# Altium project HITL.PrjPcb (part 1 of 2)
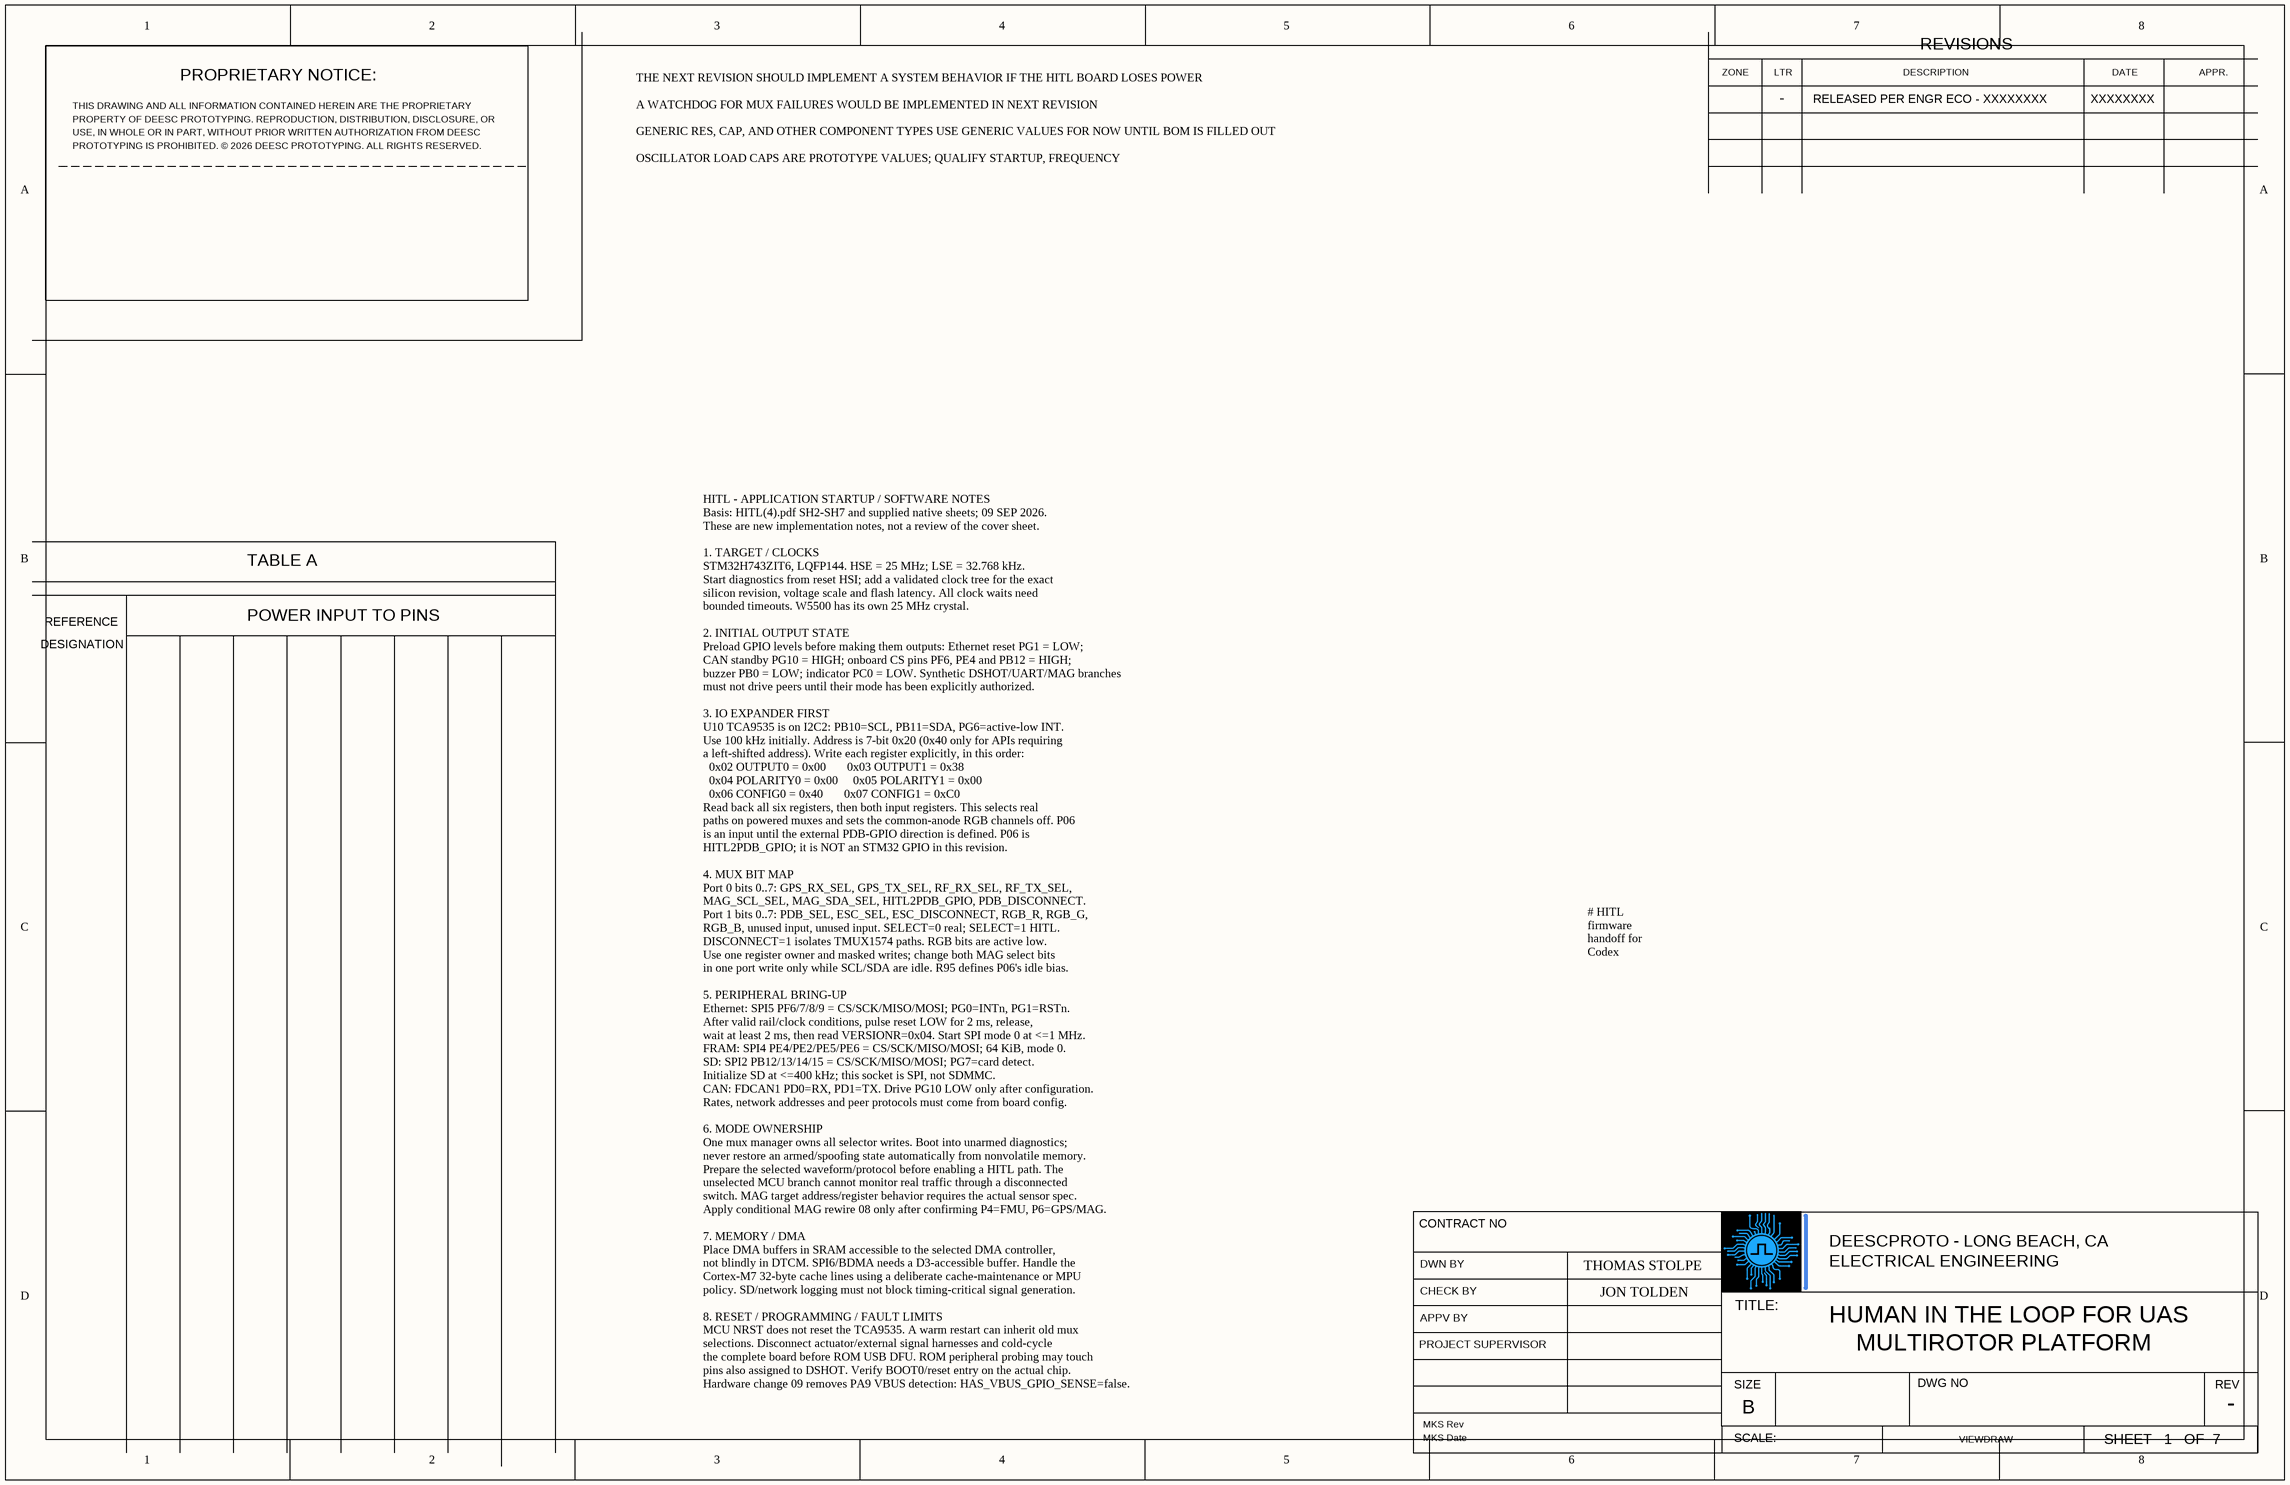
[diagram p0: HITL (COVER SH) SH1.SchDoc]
7 sheets, 198 parts. Net scope: global (net labels, ports and power ports of the same name join across sheets).
Board file: HITL R DRAFT 3 PCB.PcbDoc
Sheets:
  HITL (COVER SH) SH1.SchDoc
  HITL (PWR) SH2.SchDoc
  HITL (MCU) SH3.SchDoc
  HITL (MUX) SH4.SchDoc
  HITL (MEMORY) SH5.SchDoc
  HITL (INTRFACE 1) SH6.SchDoc
  HITL (INTRFACE 2) SH7.SchDoc

## Sheet HITL (COVER SH) SH1.SchDoc
size Tabloid; SheetNumber: 1; SheetTotal: 7

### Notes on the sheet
- THE NEXT REVISION SHOULD IMPLEMENT A SYSTEM BEHAVIOR IF THE HITL BOARD LOSES POWER
- A WATCHDOG FOR MUX FAILURES WOULD BE IMPLEMENTED IN NEXT REVISION
- GENERIC RES, CAP, AND OTHER COMPONENT TYPES USE GENERIC VALUES FOR NOW UNTIL BOM IS FILLED OUT
- OSCILLATOR LOAD CAPS ARE PROTOTYPE VALUES; QUALIFY STARTUP, FREQUENCY
- RELEASED PER ENGR ECO - XXXXXXXX
- XXXXXXXX
- # HITL firmware handoff for Codex
  **Board baseline:** `HITL(4).pdf`, SH2-SH7; native source cross-check dated 09 September 2026. This is a hardware contract and implementation plan, not completed or tested firmware. The separate hardware report contains only edit items 01-10. No cover-sheet review is included.
  ## 1. Source boundary and build profile
  Five circuit sources are the `(4).SchDoc` versions: power SH2, MCU SH3, mux SH4, memory SH5, connectors SH7. The latest supplied SH6 native is `(3).SchDoc`. Its R29 is DNI while the current PDF shows 10 kOhm; hardware change 10 proposes a fitted 0-ohm ground strap and requires synchronized source/BOM/PDF. Do not merge the unrelated PODIUM PDB into this board definition. [S01, N2-N7]
  Create an explicit board revision/profile in the project. The post-edit profile must record these dependencies:
  | Capability / hardware option | Required software meaning |
  | --- | --- |
  | Change 06, new R95 fitted | P06's isolated branch has a 10 kOhm pull-down; P06 direction is still not automatically an output. |
  | Change 08, conditional MAG rewire | Set `MAG_COMMON_SIDE=FMU_IN` only after P4=FMU and P6=real GPS/MAG are physically confirmed and the rewire is applied. Otherwise disable MAG emulation pending an approved alternative harness contract. |
  | Change 09, R1 and D1 not fitted | Set `HAS_VBUS_GPIO_SENSE=false`. PA9 cannot report USB attachment in this population. |
  | No external hardware watchdog / bypass | Software must not advertise guaranteed real-path control after HITL power loss or an unresponsive expander. |
  | USB programming use | ROM DFU is the programming path; no application USB data class is requested by this handoff. |
  The MCU is **STM32H743ZIT6, LQFP144**. The Ethernet controller is an external **W5500 on SPI5**, not an RMII PHY attached to the STM32 Ethernet MAC. SD is **SPI2**, not SDMMC. FRAM is **SPI4**. An I2C2 TCA9535 controls switch selection and RGB. These are actual schematic assignments; firmware policy below is a proposed implementation baseline. [N3-N6]
  The eFuses select USB/PDB power autonomously. Their fault/current/enable nodes are not routed to MCU measurement/control pins in this drawing. Do not fabricate software rail-current telemetry, programmable eFuse thresholds, or accessory power switches. External +5 V/+3.3 V connector pins are powered directly from those rails. [N2, N7]
  ## 2. Project setup and startup sequence
  Generate a clean STM32H743ZIT6 project and check in the `.ioc`, toolchain/package versions, linker script, board pin definitions and populated-hardware profile. Use CMSIS/HAL deliberately; RTOS use is optional. Peripheral ownership, timeout handling and deterministic output behavior matter more than the choice of scheduler.
  ### Stage A - establish a diagnostic state
  At reset, use the internal HSI clock to begin diagnostics. The populated HSE is **25 MHz** and LSE is **32.768 kHz**. Set `HSE_VALUE`/`LSE_VALUE` accordingly and configure the HSE as a crystal, not an external bypass clock. Oscillator waits must time out; an unavailable LSE must not hang programming or basic diagnostics. Log the chip revision and clock failure state. [N3; D15]
  Do not select 480 MHz merely because the library description says 480 MHz. Confirm the exact silicon revision, applicable errata, supply mode, voltage scale, flash latency, PLL limits and bus/kernel prescalers. Choose the validated operating point needed by measured workload. Derive each timer/SPI/I2C/UART kernel frequency from the actual clock tree; an APB peripheral clock is not always its timer clock. [D15, D16]
  Preload output latches before changing GPIO modes: PF6/PE4/PB12 CS high; PG1 Ethernet reset low; PG10 CAN standby high; PC0 indicator low; PB0 buzzer low. Other external chip selects become high before their SPI peripheral is enabled, once peer voltage/power is known. Initially disable timer output enables and UART transmitters on synthetic branches; use high-impedance GPIO states rather than transmitting a guessed neutral value. Maintain SWD access.
  ### Stage B - establish switch ownership before external traffic
  Initialize I2C2 at a conservative **100 kHz** and address U10 at **7-bit 0x20**. Some STM32 HAL calls expect `0x20 << 1`; use the address form expected by the actual API, not a mixture. Apply the explicit register sequence in Section 4 and compare readback. An I2C ACK alone does not prove correct pin state. [N4; D06]
  The application should start **unarmed**. Real-path selection is not an instruction to generate actuator commands. Do not initialize synthetic UART/timer outputs and assume all switches have just reset; a warm MCU reset may leave the expander latched in a previous mode. Testing initially requires external actuator harnesses disconnected.
  ### Stage C - independent peripheral diagnostics
  Bring up Ethernet, FRAM, SD and CAN separately with bounded transactions. Report each failure independently. SD absence or an unplugged Ethernet cable must not stop the scheduler or mutate mux selection. No startup error should cause an automatic transition into a synthetic-output mode.
  ### Stage D - explicit operating authorization
  Enable an emulation channel only after its peer pin directions, supply level, timing, protocol configuration and hardware profile are known. The host command must identify the intended test mode. Persist configuration with a version and CRC, but do not restore the last armed state automatically. Settings that are absent or incompatible should prevent that mode from arming.
  ## 3. MCU pin contract
  Physical pin numbers below are for the **144-pin** package, not connector numbers. Named nets are extracted from N3. AF selections were checked against the STM32 alternate-function tables, but a complete CubeMX/clock/DMA build is still required. Software-controlled CS rows deliberately use GPIO rather than hardware NSS. [N3; D15]
  | MCU port | Pin | Net | Function | AF | Use |
  | --- | --- | --- | --- | --- | --- |
  | PF6 | 18 | ETH_SCSN | SPI5 CS | GPIO | W5500 CS, active low |
  | PF7 | 19 | ETH_SCLK | SPI5 SCK | 5 | W5500 clock |
  | PF8 | 20 | ETH_MISO | SPI5 MISO | 5 | W5500 -> MCU |
  | PF9 | 21 | ETH_MOSI | SPI5 MOSI | 5 | MCU -> W5500 |
  | PG0 | 56 | ETH_INTn | EXTI / input | GPIO | W5500 INTn, active low |
  | PG1 | 57 | ETH_RSTn | Reset output | GPIO | W5500 RSTn, active low |
  | PE2 | 1 | SPI4_SCK | SPI4 SCK | 5 | FRAM clock |
  | PE5 | 4 | SPI4_MISO | SPI4 MISO | 5 | FRAM -> MCU |
  | PE6 | 5 | SPI4_MOSI | SPI4 MOSI | 5 | MCU -> FRAM |
  | PE4 | 3 | FRAM_CS | SPI4 CS | GPIO | FRAM CS, active low |
  | PB12 | 73 | SD_DATA3 | SPI2 CS | GPIO | SD DAT3/CS, active low |
  | PB13 | 74 | SD_CLK | SPI2 SCK | 5 | SD clock |
  | PB14 | 75 | SD_DATA0 | SPI2 MISO | 5 | SD DAT0 -> MCU |
  | PB15 | 76 | SD_CMD | SPI2 MOSI | 5 | MCU -> SD CMD |
  | PG7 | 92 | SD_DET | Card-detect input | GPIO | External pull-up; verify insertion polarity |
  | PB10 | 69 | IO_EXP_SCL | I2C2 SCL | 4 | Expander bus, MCU controller |
  | PB11 | 70 | IO_EXP_SDA | I2C2 SDA | 4 | Expander bus, open drain |
  | PG6 | 91 | IO_EXP_INT | EXTI / input | GPIO | Expander INT, active low |
  | PA8 | 100 | HITL_MAG_SCL | I2C3 SCL | 4 | MAG emulation bus; target role |
  | PC9 | 99 | HITL_MAG_SDA | I2C3 SDA | 4 | MAG emulation bus; open drain |
  | PE9 | 60 | HITL_DSHOT1 | TIM1 CH1 | 1 | HITL DSHOT1 branch |
  | PE11 | 64 | HITL_DSHOT2 | TIM1 CH2 | 1 | HITL DSHOT2 branch |
  | PE13 | 66 | HITL_DSHOT3 | TIM1 CH3 | 1 | HITL DSHOT3 branch |
  | PE14 | 67 | HITL_DSHOT4 | TIM1 CH4 | 1 | HITL DSHOT4 branch |
  | PB6 | 136 | FMU_UART1_TX | USART1 TX | 7 | Direct FMU telemetry |
  | PB7 | 137 | FMU_UART1_RX | USART1 RX | 7 | Direct FMU telemetry |
  | PE8 | 59 | HITL_PDB_UART_TX | UART7 TX | 7 | PDB synthetic UART branch |
  | PE7 | 58 | HITL_PDB_UART_RX | UART7 RX | 7 | PDB synthetic UART branch |
  | PE1 | 142 | HITL_RF_UART_TX | UART8 TX | 8 | RF synthetic UART branch |
  | PE0 | 141 | HITL_RF_UART_RX | UART8 RX | 8 | RF synthetic UART branch |
  | PD14 | 85 | UART8_CTS | UART8 CTS | 8 | Test point only; flow control disabled initially |
  | PD15 | 86 | UART8_RTS | UART8 RTS | 8 | Test point only; flow control disabled initially |
  | PC6 | 96 | HITL_GPS_TX | USART6 TX | 7 | GPS synthetic UART branch |
  | PC7 | 97 | HITL_GPS_RX | USART6 RX | 7 | GPS synthetic UART branch |
  | PD0 | 114 | CAN_RX | FDCAN1 RX | 9 | TCAN1042 RXD |
  | PD1 | 115 | CAN_TX | FDCAN1 TX | 9 | TCAN1042 TXD |
  | PG10 | 125 | CAN_STB | Standby output | GPIO | CAN_STB: high = standby |
  | PB0 | 46 | BUZZER | TIM3 CH3 | 2 | Q1 buzzer drive, active high |
  | PC0 | 26 | LED | LED output | GPIO | D6 blue LED, active high |
  | PA11 | 103 | DOUT_N | USB OTG FS DM | 10 | USB programming data |
  | PA12 | 104 | DOUT_P | USB OTG FS DP | 10 | USB programming data |
  | PA9 | 101 | USB_VBUS_SNS | VBUS input option | GPIO | No USB presence sensing after hardware change 09 |
  | PA4 | 40 | SPI1_CS | SPI1 CS | GPIO | External connector P5 |
  | PA5 | 41 | SPI1_SCK | SPI1 SCK | 5 | External connector P5 |
  | PA6 | 42 | SPI1_MISO | SPI1 MISO | 5 | External connector P5 |
  | PA7 | 43 | SPI1_MOSI | SPI1 MOSI | 5 | External connector P5 |
  | PA15 | 110 | SPI3_CS | SPI3 CS | GPIO | External connector P7 |
  | PC10 | 111 | SPI3_SCK | SPI3 SCK | 6 | External connector P7 |
  | PC11 | 112 | SPI3_MISO | SPI3 MISO | 6 | External connector P7 |
  | PC12 | 113 | SPI3_MOSI | SPI3 MOSI | 6 | External connector P7 |
  | PG8 | 93 | SPI6_CS | SPI6 CS | GPIO | PG8 is software CS, NOT SPI6 hardware NSS |
  | PG13 | 128 | SPI6_SCK | SPI6 SCK | 5 | External connector P10 |
  | PG12 | 127 | SPI6_MISO | SPI6 MISO | 5 | External connector P10 |
  | PG14 | 129 | SPI6_MOSI | SPI6 MOSI | 5 | External connector P10 |
  | PB8 | 139 | I2C1_SCL | I2C1 SCL | 4 | External connector J7 |
  | PB9 | 140 | I2C1_SDA | I2C1 SDA | 4 | External connector J7 |
  | PB5 | 135 | I2C1_GPIO | Auxiliary GPIO | GPIO | I2C1_GPIO test point; not serial data |
  | PD12 | 81 | I2C4_SCL | I2C4 SCL | 4 | External connector J8 |
  | PD13 | 82 | I2C4_SDA | I2C4 SDA | 4 | External connector J8 |
  | PA0 | 34 | UART4_TX | UART4 TX | 8 | External connector P12 |
  | PA1 | 35 | UART4_RX | UART4 RX | 8 | External connector P12 |
  | PD8 | 77 | USART3_TX | USART3 TX | 7 | External connector P13 |
  | PD9 | 78 | USART3_RX | USART3 RX | 7 | External connector P13 |
  | PA2 | 36 | USART2_TX | USART2 TX | 7 | External connector P14 |
  | PA3 | 37 | USART2_RX | USART2 RX | 7 | External connector P14 |
  | PA13(JTMS-SWDIO) | 105 | SWDIO | SWDIO | 0 | Debugger reserved |
  | PA14(JTCK/SWCLK) | 109 | SWCLK | SWCLK | 0 | Debugger reserved |
  | PB3(JTDO/TRACESWO) | 133 | SWO | SWO | 0 | Optional debugger trace |
  The spare breakout signals are PF2/PF3/PF4/PF5/PF10, PC1, PC2_C, PC3_C, PC4/PC5, PB1, PF11/PF12, PE12, PF14/PF15. **PC2_C/PC3_C are analog-switch pads**, so a digital-use plan must explicitly handle the relevant internal analog-switch configuration and electrical/speed restrictions. Do not silently treat them as ordinary unrestricted GPIO. PF15 is a spare breakout here, not `HITL2PDB_GPIO`. [N3, N7; D15]
  ## 4. TCA9535 register and bit contract
  A0/A1/A2 are tied low. U10 has a 7-bit address of 0x20. It does not share the external I2C1/I2C4 connectors. Software must have **one owner** for its output shadow registers; LEDs and mux tasks must not overwrite one another's bits. Use locked masked updates rather than whole-port writes from unrelated drivers. [N4]
  | Register | Address | Initial value | Interpretation |
  | --- | --- | --- | --- |
  | OUTPUT0 | 0x02 | 0x00 | All real-path selects low; PDB disconnect low; P06 latch low. |
  | OUTPUT1 | 0x03 | 0x38 | PDB/ESC selects low, ESC disconnect low, R/G/B cathodes high (off). |
  | POLARITY0 | 0x04 | 0x00 | Input readings not inverted. |
  | POLARITY1 | 0x05 | 0x00 | Input readings not inverted. |
  | CONFIG0 | 0x06 | 0x40 | P06 input; other port-0 bits outputs. |
  | CONFIG1 | 0x07 | 0xC0 | P16/P17 inputs; other port-1 bits outputs. |
  Write OUTPUT0 and OUTPUT1 before CONFIG0/CONFIG1. Write the two polarity registers explicitly. Read back all six registers and then INPUT0 (0x00) and INPUT1 (0x01). Do not issue a six-byte burst assuming the address pointer walks through every register; use explicitly addressed operations appropriate to this device. The mapping and initial values are board-specific calculations from the native wiring. [N4; D06]
  | Port.bit | U10 pin | Net | Meaning |
  | --- | --- | --- | --- |
  | P0.0 | 4 | GPS_RX_SEL | 0 real / 1 HITL |
  | P0.1 | 5 | GPS_TX_SEL | 0 real / 1 HITL |
  | P0.2 | 6 | RF_RX_SEL | 0 real / 1 HITL |
  | P0.3 | 7 | RF_TX_SEL | 0 real / 1 HITL |
  | P0.4 | 8 | MAG_SCL_SEL | 0 real / 1 HITL |
  | P0.5 | 9 | MAG_SDA_SEL | 0 real / 1 HITL |
  | P0.6 | 10 | HITL2PDB_GPIO | PDB GPIO data branch; input until ownership is defined |
  | P0.7 | 11 | PDB_DISCONNECT | 1 isolates U9 |
  | P1.0 | 13 | PDB_SEL | 0 real / 1 HITL |
  | P1.1 | 14 | ESC_SEL | 0 real / 1 HITL |
  | P1.2 | 15 | ESC_DISCONNECT | 1 isolates U7 |
  | P1.3 | 16 | RGB_R | 0 red on |
  | P1.4 | 17 | RGB_G | 0 green on |
  | P1.5 | 18 | RGB_B | 0 blue on |
  | P1.6 | 19 | Unnamed / R52 | Input with 10 kOhm pull-down |
  | P1.7 | 20 | Unnamed / R53 | Input with 10 kOhm pull-down |
  PG6 receives active-low INT. Latch an event in its ISR, then service the input registers outside the ISR. Define debounce/edge behavior for any external P06 signal. TCA9535 outputs are not general-purpose open-drain outputs; an external bidirectional wire needs a documented ownership strategy before changing P06 into an output. It is unsuitable as a high-rate timing generator. [N4; D06]
  The normal baseline above has both disconnect bits low. A separate **bench isolation** state can set OUTPUT0=0x80 and OUTPUT1=0x3C with the same direction masks; that intentionally opens the ESC and PDB paths. Use it only as an explicit operator-selected test state, not a supposedly transparent default. All numeric mode masks need unit tests against this bit table.
  ## 5. Switch paths and safe mode changes
  ### Actual paths
  | Switch | Common/output endpoint | SEL=0 | SEL=1 |
  | --- | --- | --- | --- |
  | U7, DSHOT channels 1-4 | DSHOTn_OUT, ESC-side | FMU_DSHOTn_IN | HITL_DSHOTn |
  | U9, PDB TX/RX/GPIO | PDB_*_IN | PDB_*_OUT | HITL_PDB_UART_TX/RX or P06 GPIO |
  | U8, RF TX/RX | RF_*_IN | RF_*_OUT | HITL_RF_UART_TX/RX |
  | U11, GPS TX/RX | GPS_*_IN | GPS_*_OUT | HITL_GPS_TX/RX |
  | U12 after conditional change 08 | MAG_*_IN, P4 FMU-side | MAG_*_OUT, P6 real device | HITL_MAG_SCL/SDA |
  U7/U9 use an active-low enable pin: the nets named `*_DISCONNECT` being high disconnect their paths. U8/U11/U12 are the **10-pin DGS** TMUX1072 variant and have no independent enable pin. Do not use the pinout or feature set of another package variant. [N4; D07, D08]
  **There is no passive monitoring connection from an unselected HITL branch.** In real mode, the relevant MCU branch is disconnected by the analog switch. Software cannot simultaneously observe both branches by configuring GPIO inputs. A requirement to record live real-path DSHOT/UART/MAG traffic while preserving pass-through needs a separately designed observation path; do not claim it is implemented by this firmware. [N4]
  ### Transition procedure
  For DSHOT/PDB changes: pause generation, reach the required protocol idle state, assert the corresponding disconnect control, confirm the register write, set the selector and configure the new driver's direction/state, then release disconnect when the selected signal is valid. No schedule may temporarily connect two push-pull transmitters. Readback verifies control registers, not an analog continuity test.
  For RF/GPS, wait for transmit-complete and an agreed idle interval; update the desired channel pair together through its one port byte. There is no extra global disable pin to call. A packet in progress can be truncated by a selector change, so discard/re-synchronize protocol framing deliberately.
  For MAG, update bits 4 and 5 together using mask 0x30 while both lines are idle. Configure the HITL I2C3 peripheral as a **target/slave** when emulating a sensor for an FMU controller. Never start a competing master transaction against the FMU. The exact sensor address, register map, clock-stretch behavior and read/write timing must come from the selected sensor/peer firmware. The board does not contain an onboard IMU/barometer/MAG that supplies those semantics automatically.
  ## 6. Peripheral implementation plans
  ### W5500 Ethernet
  Use SPI5 mode 0, MSB first, eight-bit transfers and GPIO CS PF6. Start at <=1 MHz for diagnostics and increase only after timing/signal validation. After the Ethernet rail and oscillator are valid, drive PG1 low for a proposed 2 ms reset pulse, release it and wait at least another 2 ms before the first SPI transaction. Extra crystal settling may be necessary. Verify VERSIONR=0x04. [N3, N6; D11]
  Integrate the official WIZnet ioLibrary through its SPI/CS and critical-section callbacks. Serialize socket/register access and defer PG0 interrupt handling to a worker. Provide explicit MAC, DHCP/static-IP, port and timeout configuration; do not ship an arbitrary duplicate MAC. A link-down event is not permission to switch hardware modes. Reset/reinitialize the device after a confirmed brownout or repeated bus failures, using a bounded retry policy. [D19; proposed application policy]
  ### FRAM
  U16 is FM25V05-GTR: 64 KiB. Use SPI4 mode 0 initially at <=1 MHz and GPIO CS PE4. Use 16-bit addresses and reject transfers beyond 0xFFFF. Issue the required write-enable command before writes; do not implement flash erase or EEPROM page-program delays as though this were a different memory. [N5; D18]
  Define a versioned record layout with bounds, payload length, CRC and a transaction/commit strategy. Boot with conservative defaults when records are corrupt or incompatible. Diagnostic logs and settings must not overwrite one another. A persistent last-mode record is informative only; it does not authorize re-arming after reset.
  ### SD logging
  Implement a SPI-mode block driver on SPI2 with GPIO CS PB12; do not generate an SDMMC pin configuration. Begin at <=400 kHz, supply startup clocks with CS high, perform the standard card-version/capacity initialization, and then select a verified operating clock. Use a suitable SPI SD driver with FatFS or another deliberate filesystem. Validate the actual card types. [N3, N5; implementation proposal]
  PG7 has an external pull-up and a socket switch to GND. Confirm whether the physical contact closes or opens on insertion rather than guessing an active polarity. Debounce it and treat errors during a transaction as possible removal. Buffer logs and flush outside the real-time output path; use bounded queues and report dropped records instead of delaying signal generation indefinitely.
  ### UART and serial emulation
  Baud rate, word length, parity, inversion, framing and peer command behavior are **not specified by this schematic**. Do not assume MAVLink, SBUS, CRSF, NMEA or a generic transparent bridge. Store a per-interface configuration, with RX ring buffers, framing/overflow counters and transmit-complete handling. UART8 RTS/CTS are only test-point signals in the drawing; hardware flow control is disabled in the initial profile. [N3, N7]
  Define TX/RX by the MCU peripheral and peer direction, not by guessing from an IN/OUT suffix. In sensor emulation, the FMU's TX reaches the HITL RX channel and HITL TX reaches the FMU RX. Confirm that mapping with an actual harness before enabling the transmitter.
  ### DSHOT
  TIM1 channels 1-4 are the proposed waveform resources. Build period and compare values from the actual timer kernel frequency; do not hard-code counts copied from another clock tree. Reserve the DMA/DMAMUX resources and verify all four channels can execute together. DSHOT rate, command framing, checksum and whether bidirectional telemetry is required must be explicit protocol inputs. Do not use GPIO bit-banging in a blocking foreground loop as the default design.
  Begin with a disconnected-load waveform test. A bidirectional implementation additionally needs output-to-input turnaround, capture timing and resource verification; it is not obtained merely by marking the hardware mux bidirectional. Input-capture access to real FMU traffic is absent while that MCU branch is switched out. [N3, N4; implementation proposal]
  ### CAN
  Use FDCAN1 PD0/PD1 and PG10 for TCAN1042 standby. Start with standby asserted; load bit timing, filters and the classical-CAN/CAN-FD policy before requesting normal operation. Bit rate and termination depend on the real bus, not the crystal annotation. Make transmit actions explicit and bounded; bus-off recovery must not emit arbitrary actuator traffic. A transceiver standby command is not removal of its +5 V supply. [N3, N6; D21]
  ### Indicators and buzzer
  PC0 drives the blue indicator active high. U10 port-1 bits 3/4/5 drive common-anode RGB cathodes active low; implement status changes through the expander owner, not independent raw I2C writes. PB0 controls Q1 and can use TIM3_CH3 for an externally driven piezo tone. All tone durations must be bounded and nonblocking. [N3, N4]
  ## 7. Memory, cache and DMA rules
  The H743 memory domains are not interchangeable for DMA. DMA1/2 cannot access the CPU's ITCM/DTCM. Select a reachable SRAM region in the linker script for each transfer engine; D2 SRAM is a common DMA1/2 option. **SPI6 uses the D3/BDMA path**, so give it a separate accessible buffer allocation (for example SRAM4 after verifying the selected engine). Do not put all peripheral buffers in one assumed universal section. [D16]
  Choose one coherent policy: either carefully maintained cacheable DMA buffers or appropriately configured noncacheable MPU regions. Cacheable buffers need 32-byte alignment and dedicated cache lines, correct TX cleaning before DMA, and correct RX ownership/invalidation before CPU use. Cache-line rounding must not discard unrelated dirty variables. Use the CMSIS cache functions and memory barriers; do not omit post-DMA invalidation simply because startup tests happened to pass. [D17]
  Complete the basic polling/interrupt bring-up before enabling caches and multiple DMA pipelines together. Record the linker section, RAM address, alignment, owner and DMA engine for every buffer. Keep ISR work short; SD/filesystem and network operations belong outside waveform-critical ISRs.
  ## 8. Reset, programming and failure semantics
  **MCU reset and whole-board power-on reset are different events.** TCA9535 can retain a previous output selection through MCU NRST. The app must establish a known state through I2C before enabling synthetic outputs, but that is not a hardware-enforced guarantee while the MCU is down. [N4; D06]
  For ROM DFU, disconnect external actuator/signal harnesses and cold-cycle the complete board so neither USB nor PDB holds the common rail alive. Use the physical BOOT0/reset entry sequence and verify the option-byte/ROM behavior on the actual device. A simple jump from application code into ROM requires a separately tested deinitialization/clock/interrupt/cache sequence and is not the initial programming method.
  The H74xxx ROM probes other interfaces as well as USB. Its SPI4 boot pin group includes PE11-PE14, overlapping this board's DSHOT assignments, and is not the application's FRAM SPI4 group. Do not rely on application mux initialization to execute while ROM owns the MCU. [D09]
  With change 09 fitted as specified, the application has no PA9 VBUS-presence input. A later self-powered USB application must obtain a qualified attachment detector before advertising that capability. ROM USB programming and an application USB class are separate requirements.
  On host timeout, malformed commands, expander errors or internal deadline violations, stop accepting new test commands, quiesce MCU-generated outputs and mark the mode invalid. Attempt an approved real-path or isolate command only when control communication is healthy. **An unreachable expander means actual mode is UNKNOWN**, not that a software state variable has forced the hardware safe. Power loss makes these muxes high impedance; neither pull-downs nor MCU watchdog firmware creates an unpowered bypass. [D07, D08]
  The eFuse latch-off variants may require input power cycling. AUXOFF is not load-side power-good, and its autonomous behavior cannot be repaired by an invented GPIO signal. Log a reset event when observable, but do not invent voltage/current values not measured on the board. [N2; D14]
  ## 9. Recommended repository and acceptance checks
  Separate modules for board pins/profile, clock/startup, I2C expander, mux manager, W5500/network, FRAM storage, SPI SD/filesystem, UART engines, MAG target emulation, DSHOT, CAN and diagnostics. A single command/mode coordinator should own transitions; drivers should return typed error results and support cancellation/timeouts.
  A host protocol should include a version, declared length, sequence identifier, integrity check, channel/mode and freshness/deadline information. Enforce range checks before writing hardware. Add an explicit bench arming step and channel permissions. These are proposed interface requirements, not an assertion that a specific host simulator protocol was supplied.
  Unit-test every bit mask and transition, SPI framing, record CRC/bounds, command validation, timeout and queue-overflow path. On hardware, demonstrate cold startup, warm MCU reset after a spoofing state, failed expander communication, host-link loss, SD removal, Ethernet reset recovery, real/synthetic endpoint selection and simultaneous timing load. Use logic-analyzer evidence before connecting actuators. Measure USB attach and DFU current with external powered accessories absent; the regulator's current rating is not a measured board load.
  Unresolved inputs that must be explicit project configuration or block the affected mode: physical P4/P6 peer contract, PDB-GPIO direction, UART protocols/rates, MAG model/address/register semantics, DSHOT rate/telemetry format, CAN topology/timing, network identity, host protocol, update deadlines and logging throughput. Do not invent these merely to get a successful compile.
  ## 10. Harness / connector map
  These contact maps are extracted from N3/N7, not assumed standard cable pinouts. `NC` means no connected net in the supplied sheet. Power contacts marked +5V/+3.3V are board rail exports unless the connector is J9, the dedicated PDB power input. They are not permission to back-power the board. Separate peer supply outputs from these contacts. J1 is a custom SWD connector, not a standard keyed ARM debug pinout.
  | Connector | Sheet | Contacts / nets |
  | --- | --- | --- |
  | J1 | SH3 | 1=NC; 2=SWCLK; 3=SWDIO; 4=GND; 5=+3.3V; 6=NRST; 7=BOOT0; 8=SWO; P1=GND (mount/shield pad); P2=GND (mount/shield pad) |
  | J9 | SH2 | 1=+5V_CONN; 2=GND |
  | P2 | SH7 | 1=FMU_DSHOT1_IN; 2=FMU_DSHOT2_IN; 3=FMU_DSHOT3_IN; 4=FMU_DSHOT4_IN; 5=GND; 6=GND (mount/shield pad); 7=GND (mount/shield pad) |
  | P3 | SH7 | 1=DSHOT1_OUT; 2=DSHOT2_OUT; 3=DSHOT3_OUT; 4=DSHOT4_OUT; 5=GND; 6=GND (mount/shield pad); 7=GND (mount/shield pad) |
  | P4 | SH7 | 1=GND; 2=GPS_RX_IN; 3=GPS_TX_IN; 4=MAG_SCL_IN; 5=MAG_SDA_IN; 6=NC; S1=GND (mount/shield pad); S2=GND (mount/shield pad) |
  | P6 | SH7 | 1=GND; 2=GPS_RX_OUT; 3=GPS_TX_OUT; 4=MAG_SCL_OUT; 5=MAG_SDA_OUT; 6=+5V; S1=GND (mount/shield pad); S2=GND (mount/shield pad) |
  | J2 | SH7 | 1=NC; 2=GND; 3=RF_RX_IN; 4=RF_TX_IN; S1=GND (mount/shield pad); S2=GND (mount/shield pad) |
  | J4 | SH7 | 1=+5V; 2=GND; 3=RF_RX_OUT; 4=RF_TX_OUT; S1=GND (mount/shield pad); S2=GND (mount/shield pad) |
  | P8 | SH7 | 1=GND; 2=PDB_TX_IN; 3=PDB_RX_IN; S1=GND (mount/shield pad); S2=GND (mount/shield pad) |
  | P11 | SH7 | 1=GND; 2=PDB_TX_OUT; 3=PDB_RX_OUT; S1=GND (mount/shield pad); S2=GND (mount/shield pad) |
  | P9 | SH7 | 1=GND; 2=FMU_UART1_TX; 3=FMU_UART1_RX; S1=GND (mount/shield pad); S2=GND (mount/shield pad) |
  | P12 | SH7 | 1=GND; 2=UART4_RX; 3=UART4_TX; S1=GND (mount/shield pad); S2=GND (mount/shield pad) |
  | P13 | SH7 | 1=GND; 2=USART3_RX; 3=USART3_TX; S1=GND (mount/shield pad); S2=GND (mount/shield pad) |
  | P14 | SH7 | 1=GND; 2=USART2_RX; 3=USART2_TX; S1=GND (mount/shield pad); S2=GND (mount/shield pad) |
  | P5 | SH7 | 1=+3.3V; 2=GND; 3=SPI1_SCK via R55 22R; 4=SPI1_CS via R56 22R; 5=SPI1_MISO; 6=SPI1_MOSI via R57 22R; S1=GND (mount/shield pad); S2=GND (mount/shield pad) |
  | P7 | SH7 | 1=+3.3V; 2=GND; 3=SPI3_SCK via R59 22R; 4=SPI3_CS via R60 22R; 5=SPI3_MISO; 6=SPI3_MOSI via R61 22R; S1=GND (mount/shield pad); S2=GND (mount/shield pad) |
  | P10 | SH7 | 1=+3.3V; 2=GND; 3=SPI6_SCK via R63 22R; 4=SPI6_CS via R64 22R; 5=SPI6_MISO; 6=SPI6_MOSI via R65 22R; S1=GND (mount/shield pad); S2=GND (mount/shield pad) |
  | J7 | SH7 | 1=+3.3V; 2=GND; 3=I2C1_SDA; 4=I2C1_SCL; S1=GND (mount/shield pad); S2=GND (mount/shield pad) |
  | J8 | SH7 | 1=+3.3V; 2=GND; 3=I2C4_SDA; 4=I2C4_SCL; S1=GND (mount/shield pad); S2=GND (mount/shield pad) |
  | J3 | SH7 | 1=+5V; 2=CANH_OUT; 3=CANL_OUT; 4=GND; S1=GND (mount/shield pad); S2=GND (mount/shield pad) |
  | J5 | SH7 | 1=+3.3V; 2=+5V; 3=PF2; 4=PF3; 5=PF4; 6=PF5; 7=PF10; 8=PC1; 9=PC2_C; 10=PC3_C; 11=GND; 12=GND; 13=GND (mount/shield pad); 14=GND (mount/shield pad) |
  | J6 | SH7 | 1=+3.3V; 2=+5V; 3=PC4; 4=PC5; 5=PB1; 6=PF11; 7=PF12; 8=PF14; 9=PF15; 10=PE12; 11=GND; 12=GND; 13=GND (mount/shield pad); 14=GND (mount/shield pad) |
  For the sensor-emulation contract proposed in hardware change 08: P4 is the FMU connector and P6 is the GPS/MAG connector. Therefore P4.3 reaches FMU RX and P4.2 receives FMU TX; P6.3 receives the real GPS TX and P6.2 goes to real GPS RX. Confirm that proposed cable orientation before applying it. `PDB_GPIO_IN` and `PDB_GPIO_OUT` are on TP22 and TP31, not extra contacts on the three-pin UART connectors. [N7]
  ## 11. References and provenance
  The native geometry extraction is a review aid, not an Altium compiler result. No firmware project, source build, real peer-board package, PCB footprint geometry or bench results were supplied. Conditional firmware/harness choices above must not be mistaken for proven physical wiring on a finished board.
  **[S01] Current drawing: HITL(4).pdf.** User upload; SH2-SH7 only. SH1 is excluded.
  **[N2] HITL (PWR) SH2(4).SchDoc.** Native power sheet; component parameters, pin numbers and wire geometry.
  **[N3] HITL (MCU) SH3(4).SchDoc.** Native MCU sheet; full physical pin allocation and component fields.
  **[N4] HITL (MUX) SH4(4).SchDoc.** Native mux sheet; switch endpoints, control bits and pull-ups.
  **[N5] HITL (MEMORY) SH5(4).SchDoc.** Native memory sheet; SPI SD and FRAM connections.
  **[N6] HITL (INTRFACE 1) SH6(3).SchDoc.** Latest supplied SH6 native is the earlier (3) file, not (4). R29 differs from current PDF.
  **[N7] HITL (INTRFACE 2) SH7(4).SchDoc.** Native connector sheet; physical contact and net assignments.
  **[D01] Bourns SRP1050WA series.** Page 1: 5R6M and 680M are different inductances and current ratings. https://www.bourns.com/docs/product-datasheets/srp1050wa.pdf
  **[D02] Diodes AP64502Q.** Pinout and application component selection; reference input bypassing. https://www.diodes.com/datasheet/download/AP64502Q.pdf
  **[D03] Samsung CL21A106KAYNNN family.** Exact E packaging option: 10 uF, 25 V, X5R, 0805, +/-10%. https://product.samsungsem.com/mlcc/CL21A106KAYNNN.do
  **[D04] Wurth 150060VS75000.** Page 1: existing orderable part emits green light. https://www.we-online.com/components/products/datasheet/150060VS75000.pdf
  **[D05] Wurth 150060BS75000.** Page 1: blue replacement; pin 1 cathode, pin 2 anode. https://www.we-online.com/components/products/datasheet/150060BS75000.pdf
  **[D06] TI TCA9535.** Pages 1, 3, 16-22: undriven input bias, register addresses, reset behavior. https://www.ti.com/lit/ds/symlink/tca9535.pdf
  **[D07] TI TMUX1072.** DGS 10-pin mapping, selector truth table and powered-off behavior. https://www.ti.com/lit/ds/symlink/tmux1072.pdf
  **[D08] TI TMUX1574.** Active-low enable and A/B selection; powered-off isolation. https://www.ti.com/lit/ds/symlink/tmux1574.pdf
  **[D09] ST AN2606 bootloader guide.** Rev.70, H74xxx section; USB DFU and bootloader pin-use table on printed p323. https://www.st.com/resource/en/application_note/an2606-stm32-microcontroller-system-memory-boot-mode-stmicroelectronics.pdf
  **[D10] ST AN4879 USB hardware guide.** GPIO VBUS detection is distinct from internal analog VBUS sensing. https://www.st.com/resource/en/application_note/an4879-introduction-to-usb-hardware-and-pcb-guidelines-using-stm32-mcus-stmicroelectronics.pdf
  **[D11] WIZnet W5500 data sheet v1.1.0.** Printed p9: pin 23 ground requirement; pp10,60: reset and PLL timing. https://docs.wiznet.io/img/products/w5500/W5500_ds_v110e.pdf
  **[D12] WIZnet integrated-magnetics reference.** This drawing does NOT specify the previously claimed 10k at pin 23; the pin is shown NC. This review follows D11 pin table. https://docs.wiznet.io/img/products/w5500/w5500_sch_v110_use_mag_.pdf
  **[D13] ST ESDAxxPxxx-1U1M TVS family.** Table 4 / p3: ESDA7P120-1U1M; package and polarity drawings. https://www.st.com/resource/en/datasheet/esda7p60-1u1m.pdf
  **[D14] TI TPS25947.** May 2026; Option 2 and raw-input transient protection. User also supplied this data sheet. https://www.ti.com/lit/ds/symlink/tps25947.pdf
  **[D15] ST STM32H743ZI data sheet.** LQFP144 physical pins, alternate functions and electrical limits. https://www.st.com/resource/en/datasheet/stm32h743zi.pdf
  **[D16] ST AN4891 system architecture.** Rev.7: memory domains and DMA access restrictions, pp8,14-16,20-22. https://www.st.com/resource/en/application_note/an4891-stm32h72x-stm32h73x-and-singlecore-stm32h74x75x-system-architecture-and-performance-stmicroelectronics.pdf
  **[D17] ST AN4839 cache guidance.** DMA/cache coherency and Cortex-M7 cache-line considerations. https://www.st.com/resource/en/application_note/an4839-level-1-cache-on-stm32f7-series-and-stm32h7-series-stmicroelectronics.pdf
  **[D18] Infineon FM25V05-GTR.** 64 KiB SPI FRAM; modes 0/3, no flash-erase operation. https://www.infineon.com/part/FM25V05-GTR
  **[D19] WIZnet ioLibrary_Driver.** Official W5500 driver and socket API integration. https://github.com/Wiznet/ioLibrary_Driver
  **[D21] TI TCAN1042H-Q1 family.** VIO variant, standby operation and CAN bus requirements. https://www.ti.com/lit/ds/symlink/tcan1042h-q1.pdf
  **Input fingerprint:** HITL(4).pdf SHA-256 `34c5cb372cfdfd0145cc53a356523c0c669ebe60bebb532489318ee68cd852f0`.
- PROJECT SUPERVISOR
- HUMAN IN THE LOOP FOR UAS
- MULTIROTOR PLATFORM
- HITL - APPLICATION STARTUP / SOFTWARE NOTES
  Basis: HITL(4).pdf SH2-SH7 and supplied native sheets; 09 SEP 2026.
  These are new implementation notes, not a review of the cover sheet.
  1. TARGET / CLOCKS
  STM32H743ZIT6, LQFP144. HSE = 25 MHz; LSE = 32.768 kHz.
  Start diagnostics from reset HSI; add a validated clock tree for the exact
  silicon revision, voltage scale and flash latency. All clock waits need
  bounded timeouts. W5500 has its own 25 MHz crystal.
  2. INITIAL OUTPUT STATE
  Preload GPIO levels before making them outputs: Ethernet reset PG1 = LOW;
  CAN standby PG10 = HIGH; onboard CS pins PF6, PE4 and PB12 = HIGH;
  buzzer PB0 = LOW; indicator PC0 = LOW. Synthetic DSHOT/UART/MAG branches
  must not drive peers until their mode has been explicitly authorized.
  3. IO EXPANDER FIRST
  U10 TCA9535 is on I2C2: PB10=SCL, PB11=SDA, PG6=active-low INT.
  Use 100 kHz initially. Address is 7-bit 0x20 (0x40 only for APIs requiring
  a left-shifted address). Write each register explicitly, in this order:
  0x02 OUTPUT0 = 0x00       0x03 OUTPUT1 = 0x38
  0x04 POLARITY0 = 0x00     0x05 POLARITY1 = 0x00
  0x06 CONFIG0 = 0x40       0x07 CONFIG1 = 0xC0
  Read back all six registers, then both input registers. This selects real
  paths on powered muxes and sets the common-anode RGB channels off. P06
  is an input until the external PDB-GPIO direction is defined. P06 is
  HITL2PDB_GPIO; it is NOT an STM32 GPIO in this revision.
  4. MUX BIT MAP
  Port 0 bits 0..7: GPS_RX_SEL, GPS_TX_SEL, RF_RX_SEL, RF_TX_SEL,
  MAG_SCL_SEL, MAG_SDA_SEL, HITL2PDB_GPIO, PDB_DISCONNECT.
  Port 1 bits 0..7: PDB_SEL, ESC_SEL, ESC_DISCONNECT, RGB_R, RGB_G,
  RGB_B, unused input, unused input. SELECT=0 real; SELECT=1 HITL.
  DISCONNECT=1 isolates TMUX1574 paths. RGB bits are active low.
  Use one register owner and masked writes; change both MAG select bits
  in one port write only while SCL/SDA are idle. R95 defines P06's idle bias.
  5. PERIPHERAL BRING-UP
  Ethernet: SPI5 PF6/7/8/9 = CS/SCK/MISO/MOSI; PG0=INTn, PG1=RSTn.
  After valid rail/clock conditions, pulse reset LOW for 2 ms, release,
  wait at least 2 ms, then read VERSIONR=0x04. Start SPI mode 0 at <=1 MHz.
  FRAM: SPI4 PE4/PE2/PE5/PE6 = CS/SCK/MISO/MOSI; 64 KiB, mode 0.
  SD: SPI2 PB12/13/14/15 = CS/SCK/MISO/MOSI; PG7=card detect.
  Initialize SD at <=400 kHz; this socket is SPI, not SDMMC.
  CAN: FDCAN1 PD0=RX, PD1=TX. Drive PG10 LOW only after configuration.
  Rates, network addresses and peer protocols must come from board config.
  6. MODE OWNERSHIP
  One mux manager owns all selector writes. Boot into unarmed diagnostics;
  never restore an armed/spoofing state automatically from nonvolatile memory.
  Prepare the selected waveform/protocol before enabling a HITL path. The
  unselected MCU branch cannot monitor real traffic through a disconnected
  switch. MAG target address/register behavior requires the actual sensor spec.
  Apply conditional MAG rewire 08 only after confirming P4=FMU, P6=GPS/MAG.
  7. MEMORY / DMA
  Place DMA buffers in SRAM accessible to the selected DMA controller,
  not blindly in DTCM. SPI6/BDMA needs a D3-accessible buffer. Handle the
  Cortex-M7 32-byte cache lines using a deliberate cache-maintenance or MPU
  policy. SD/network logging must not block timing-critical signal generation.
  8. RESET / PROGRAMMING / FAULT LIMITS
  MCU NRST does not reset the TCA9535. A warm restart can inherit old mux
  selections. Disconnect actuator/external signal harnesses and cold-cycle
  the complete board before ROM USB DFU. ROM peripheral probing may touch
  pins also assigned to DSHOT. Verify BOOT0/reset entry on the actual chip.
  Hardware change 09 removes PA9 VBUS detection: HAS_VBUS_GPIO_SENSE=false.
  USB is for programming; measure attach/DFU current with accessories absent.
  There is no unpowered bypass or hardware watchdog override in this revision.
  At mux power loss all signal paths isolate. On a control-bus fault, quiesce
  MCU-generated outputs and report mode UNKNOWN; do not claim software can
  force real pass-through when the expander is unreachable.
- -
- 7

## Sheet HITL (PWR) SH2.SchDoc
size Tabloid; SheetNumber: 2; SheetTotal: 7
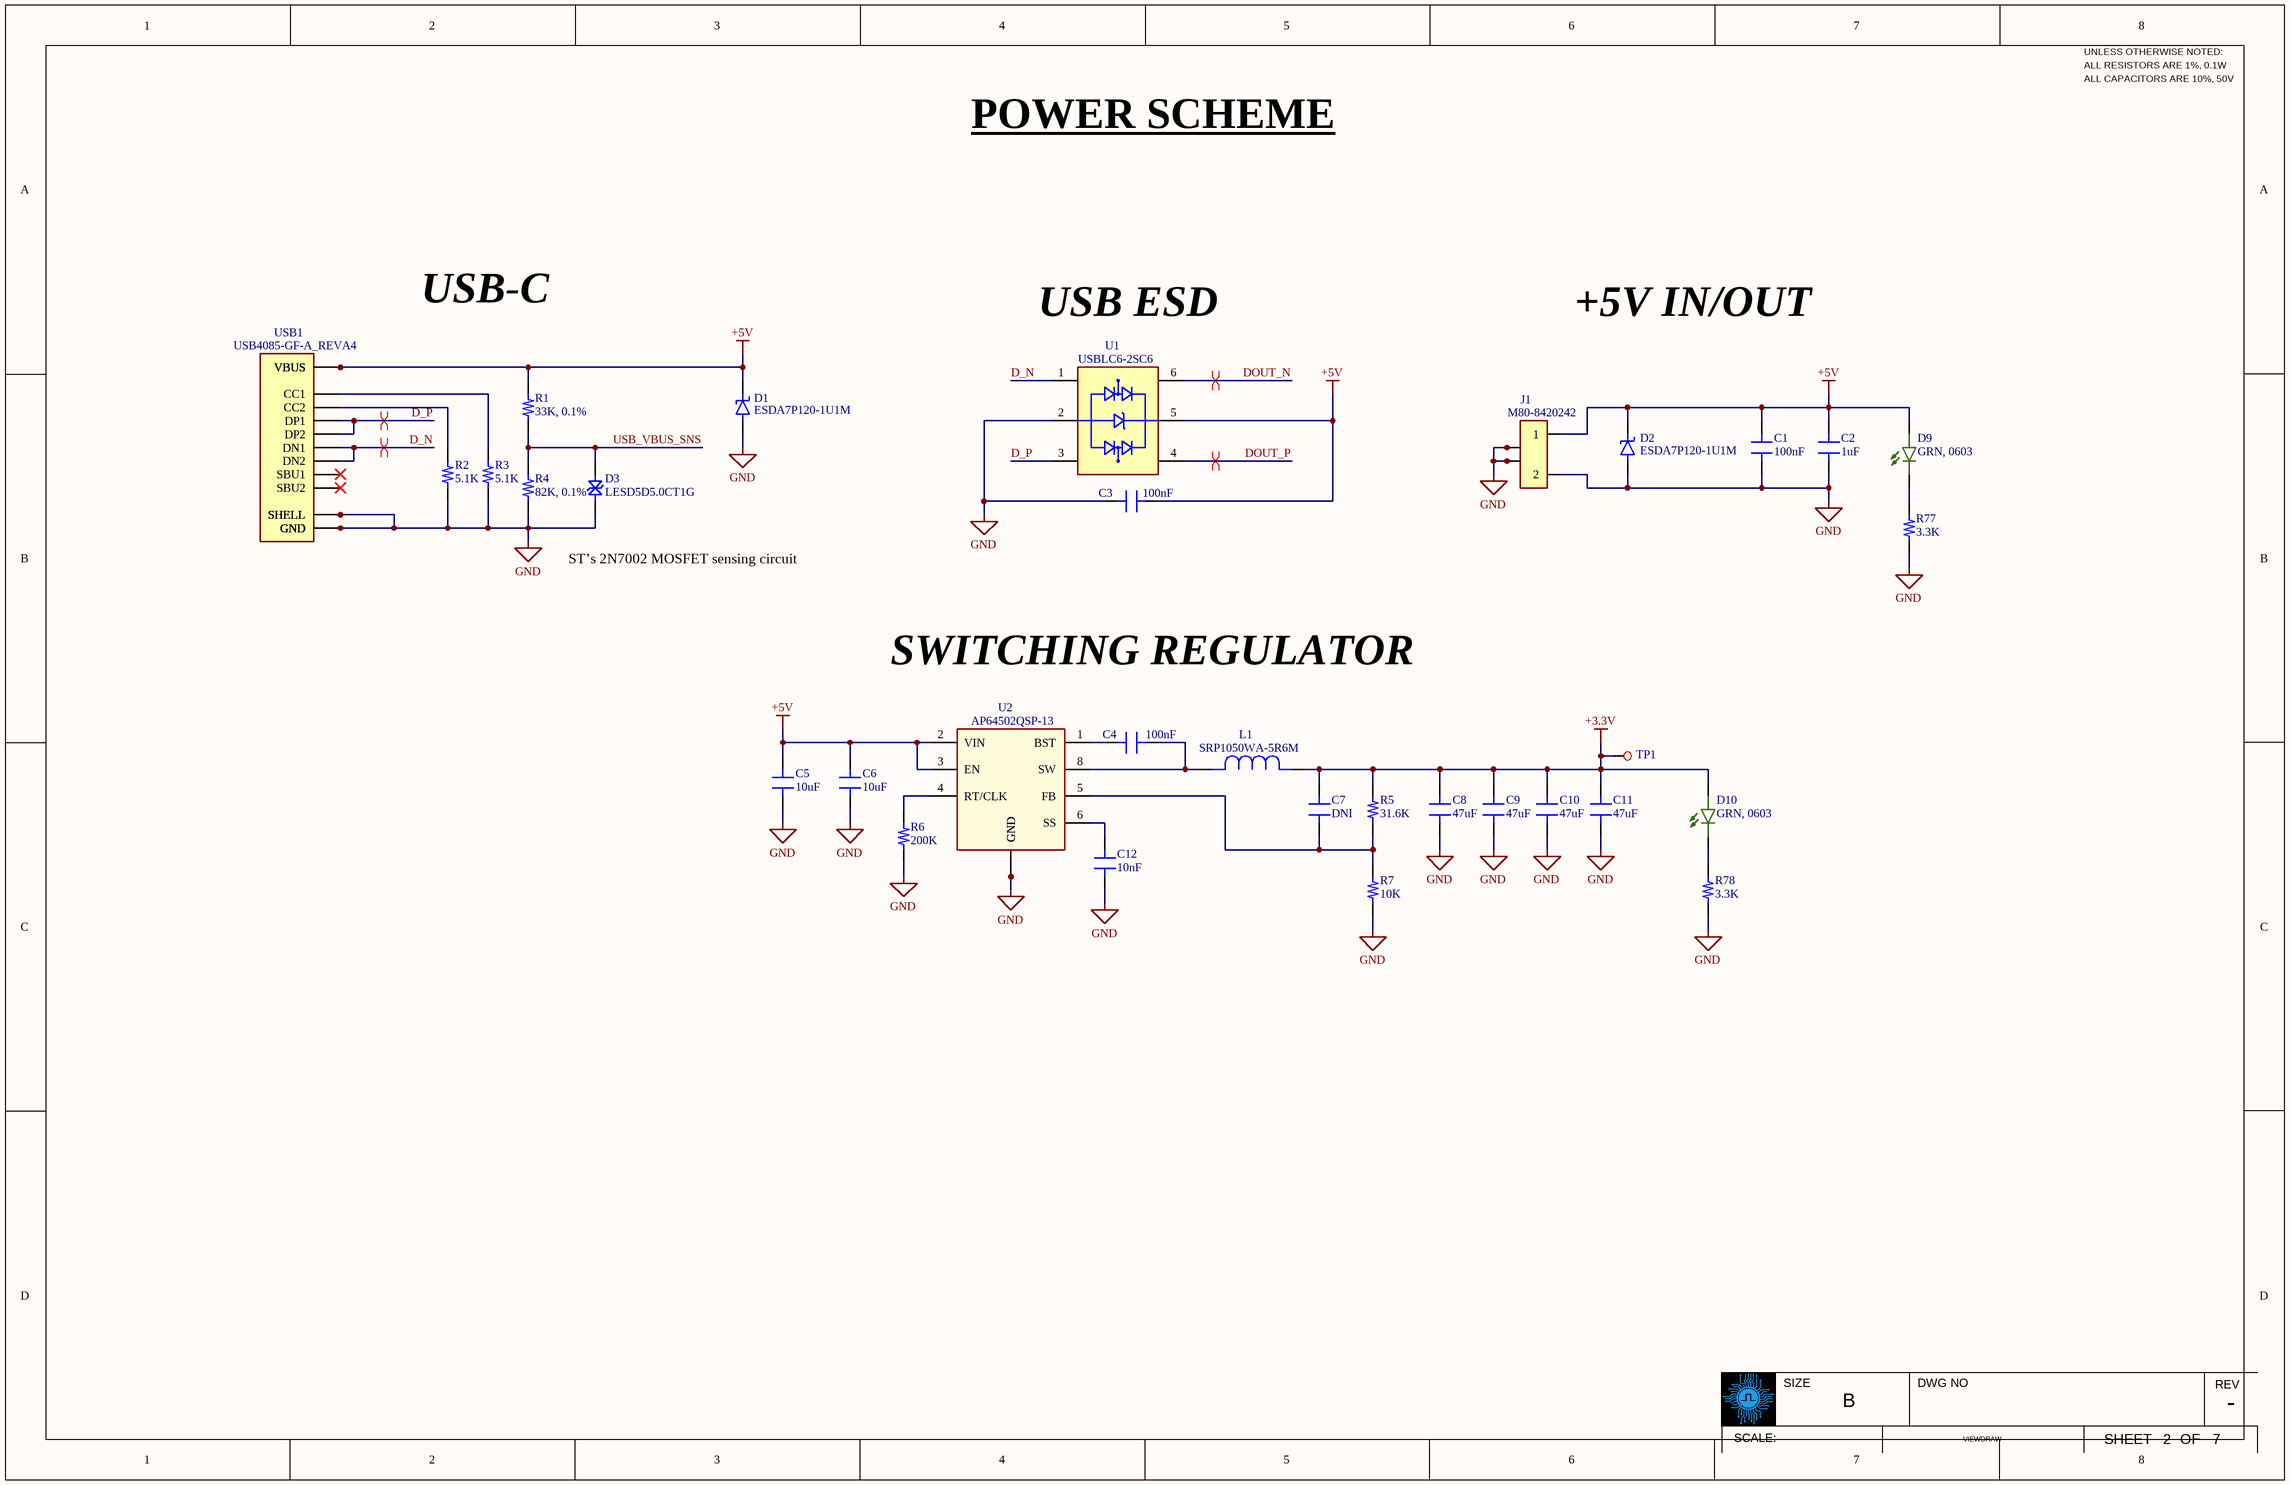
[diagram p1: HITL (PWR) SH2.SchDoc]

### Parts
C1  100nF  [0603]
C2  1uF  [0603]
C3  100nF  [0603]
C4  100nF  [0603]
C5  10uF  [0805]
C6  10uF  [0805]
C7  DNI  [0603]
C8  47uF  [1206]
C9  47uF  [1206]
C10  47uF  [1206]
C11  47uF  [1206]
C12  10nF  [0603]
D1  ESDA7P120-1U1M  [TVS_ESDA7P120-1U1M]
D2  ESDA7P120-1U1M  [TVS_ESDA7P120-1U1M]
D3  LESD5D5.0CT1G  [TVS_LESD5D5.0CT1G]
D9  GRN, 0603  [0603_LED]
D10  GRN, 0603  [0603_LED]
J1  M80-8420242  [HARWIN_M80-8420242]
L1  SRP1050WA-5R6M  [IND_SRP1050_BRN]
R1  33K, 0.1%  [0603]
R2  5.1K  [0603]
R3  5.1K  [0603]
R4  82K, 0.1%  [0603]
R5  31.6K  [0603]
R6  200K  [0603]
R7  10K  [0603]
R77  3.3K  [0603]
R78  3.3K  [0603]
TP1  TESTPAD  [TESTPAD]  (value not drawn)
U1  USBLC6-2SC6  [SOT95P280X145-6N]
U2  AP64502QSP-13  [SO-8EP_DIO]
USB1  USB4085-GF-A_REVA4  [GCT_USB4085-GF-A_REVA4]

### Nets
+3.3V: C7.2 C8.2 C9.2 C10.2 C11.2 D10.2(POS) L1.1 R5.2 TP1.1
+5V: C1.2 C2.2 C3.1 C5.2 C6.2 D1.1 D2.1 D9.2(POS) J1.1 R1.2 U1.5(VBUS) U2.2(VIN) U2.3(EN) USB1.A4(VBUS) USB1.A9(VBUS) USB1.B4(VBUS) USB1.B9(VBUS)
GND: C1.1 C2.1 C3.2 C5.1 C6.1 C8.1 C9.1 C10.1 C11.1 C12.1 D1.2 D2.2 D3.2 J1.2 J1.SH1(SHIELD) J1.SH2(SHIELD) J1.SH3(SHIELD) J1.SH4(SHIELD) R2.1 R3.1 R4.1 R6.1 R7.1 R77.1 R78.1 U1.2(GND) U2.7(GND) U2.9(GND) USB1.A1(GND) USB1.A12(GND) USB1.B1(GND) USB1.B12(GND) USB1.S1(SHELL) USB1.S2(SHELL) USB1.S3(SHELL) USB1.S4(SHELL)
D_N: U1.1(I/O1_IN) USB1.A7(DN1) USB1.B7(DN2)
D_P: U1.3(I/O2_IN) USB1.A6(DP1) USB1.B6(DP2)
DOUT_N: U1.6(I/O1_OUT)
DOUT_P: U1.4(I/O2_OUT)
USB_VBUS_SNS: D3.1 R1.1 R4.2
NetC4_1: C4.1 U2.1(BST)
NetC4_2: C4.2 L1.2 U2.8(SW)
NetC7_1: C7.1 R5.1 R7.2 U2.5(FB)
NetC12_2: C12.2 U2.6(SS)
NetD9_1: D9.1(NEG) R77.2
NetD10_1: D10.1(NEG) R78.2
NetR2_2: R2.2 USB1.B5(CC2)
NetR3_2: R3.2 USB1.A5(CC1)
NetR6_2: R6.2 U2.4(RT/CLK)

Not connected (* = marked no-connect by the designer): USB1 A8(SBU1)* B8(SBU2)*

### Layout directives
differential pair: D_P, DOUT_N, DOUT_P
differential pair; differential pair class USB_LINES; net class *: D_N

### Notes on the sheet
- POWER SCHEME
- USB-C
- USB ESD
- +5V IN/OUT
- (near D1) THE ENTIRE VBUS NET MUST BE <10uF
- ST’s 2N7002 MOSFET sensing circuit
- MATING CONNECTOR: M80-8980205
- SWITCHING REGULATOR
- -
- 2
- 7

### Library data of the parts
C1-C4 C7 C12 = 0603_C
C5 = 0805_CAP: 0805 cap; MF: AVX
C6 = 0805_CAP: 0805 cap; MF: AVX; MP: 08055C102K4T2A
C8-C11 = 1206_CAP: 1206 CAP
D1 D2 = ESDA7P120-1U1M: MF: {'manufacturer': u'STMicroelectronics'}
D3 = LESD5D5.0CT1G: Transient Voltage Suppressors for ESD Protection; MF: Leshan Radio Co.
D9 D10 = 0603_LED_GRN: MF: Wurth Elektronik; MP: 150060VS75000
L1 = SRP1050WA-5R6M: Description; Manufacturer_Name: Bourns Electronics; Type: Fixed Inductors
R1-R7 R77 R78 = 0603_R
U1 = USBLC6-2SC6: 17V Clamp 5A (8/20Âµs) Ipp Tvs Diode Surface Mount SOT-23-6; MF: STMicroelectronics
U2 = AP64502QSP-13: Description; Manufacturer_Name: Diodes Inc
USB1 = USB4085-GF-A_REVA4: USB-C (USB TYPE-C) USB 2.0 Receptacle Connector 24 (16+8 Dummy) Position Through Hole, Right Angle, low cost, 3.46mm profile, 16 pin, horizontal, Top mount; MF: Global Connector Technology

## Sheet HITL (MCU) SH3.SchDoc
size Tabloid; SheetNumber: 3; SheetTotal: 7
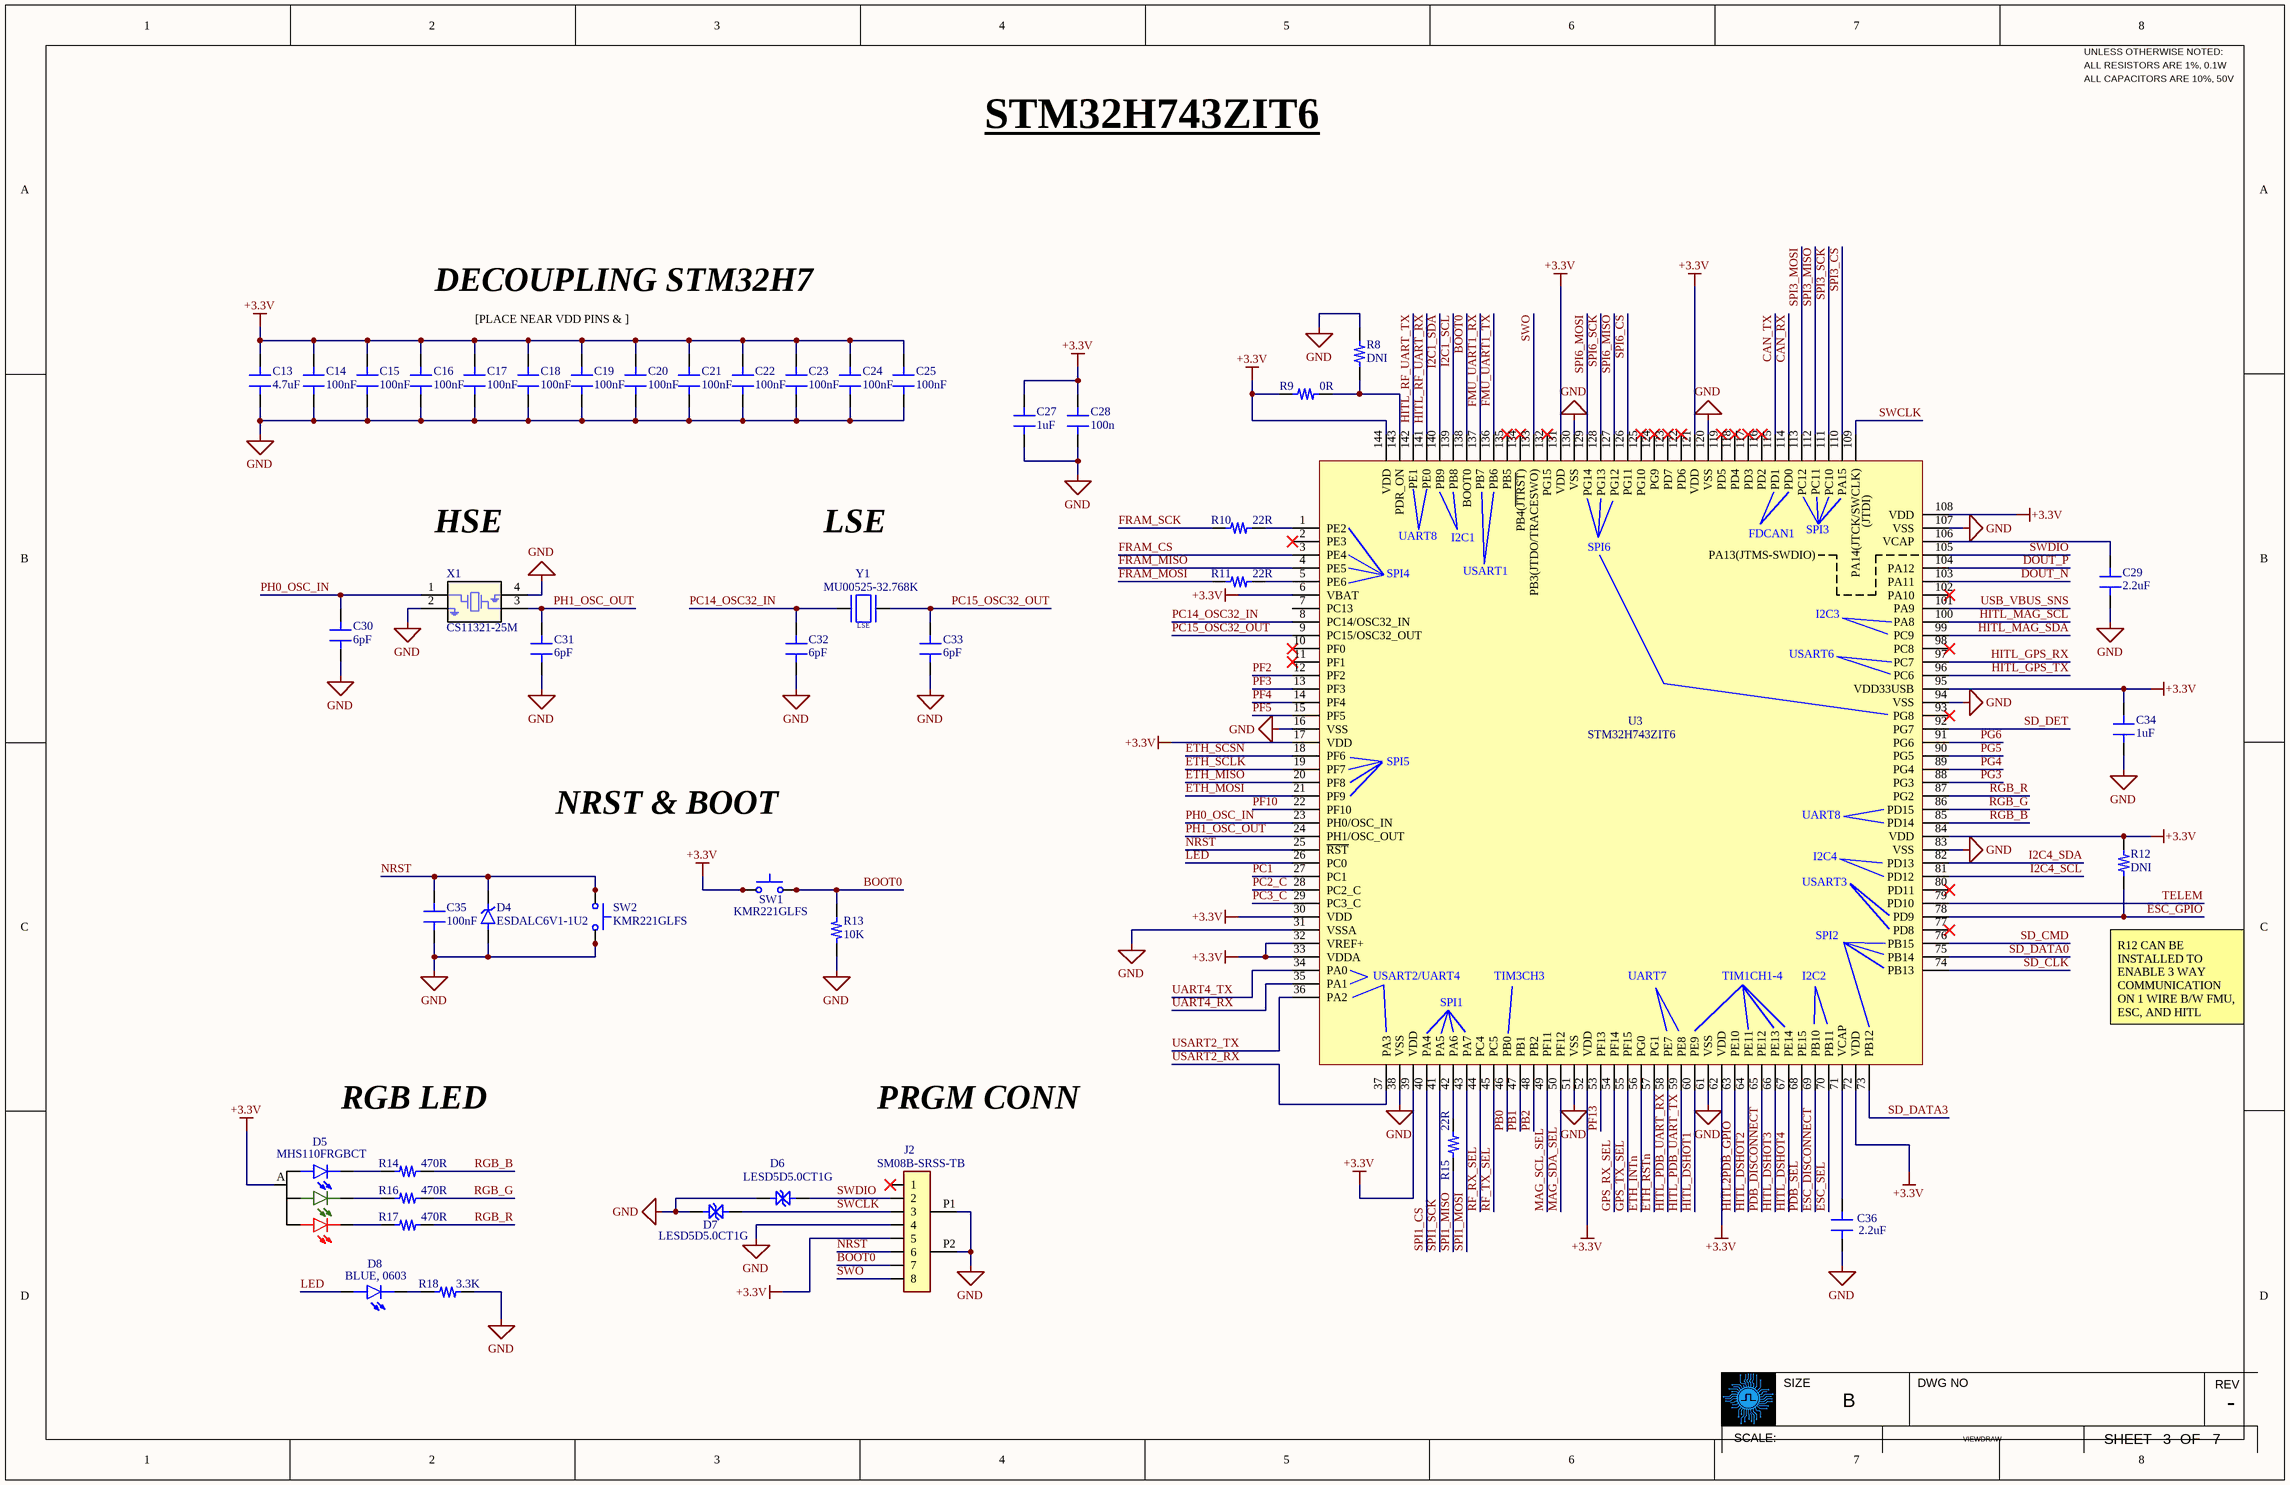
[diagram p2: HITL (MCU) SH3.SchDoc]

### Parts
C13  4.7uF  [0603]
C14  100nF  [0603]
C15  100nF  [0603]
C16  100nF  [0603]
C17  100nF  [0603]
C18  100nF  [0603]
C19  100nF  [0603]
C20  100nF  [0603]
C21  100nF  [0603]
C22  100nF  [0603]
C23  100nF  [0603]
C24  100nF  [0603]
C25  100nF  [0603]
C27  1uF  [0603]
C28  100n  [0603]
C29  2.2uF  [0603]
C30  6pF  [0603]
C31  6pF  [0603]
C32  6pF  [0603]
C33  6pF  [0603]
C34  1uF  [0603]
C35  100nF  [0603]
C36  2.2uF  [0603]
D4  ESDALC6V1-1U2  [DIODE_ESDALC6V1-1U2]
D5  MHS110FRGBCT  [MHS110FRGBCT]
D6  LESD5D5.0CT1G  [TVS_LESD5D5.0CT1G]
D7  LESD5D5.0CT1G  [TVS_LESD5D5.0CT1G]
D8  BLUE, 0603  [0603_LED]
J2  SM08B-SRSS-TB  [JST_SM08B-SRSS-TB]
R8  DNI  [0603]
R9  0R  [0603]
R10  22R  [0603]
R11  22R  [0603]
R12  DNI  [0603]
R13  10K  [0603]
R14  470R  [0603]
R15  22R  [0603]
R16  470R  [0603]
R17  470R  [0603]
R18  3.3K  [0603]
SW1  KMR221GLFS  [SW_KMR221GLFS]
SW2  KMR221GLFS  [SW_KMR221GLFS]
U3  STM32H743ZIT6  [QFP50P2200X2200X160-144N]
X1  CS11321-25M  [CS11321-25M_NDK]
Y1  MU00525-32.768K  [XTAL_NX3215SA-32.768KHZ-EXS00A-MU00525]

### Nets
+3.3V: C13.2 C14.2 C15.2 C16.2 C17.2 C18.2 C19.2 C20.2 C21.2 C22.2 C23.2 C24.2 C25.2 C27.2 C28.2 C34.2 D5.A J2.5 R9.1 R12.2 SW1.1 SW1.4 U3.6(VBAT) U3.17(VDD) U3.30(VDD) U3.32(VREF+) U3.33(VDDA) U3.39(VDD) U3.52(VDD) U3.62(VDD) U3.72(VDD) U3.84(VDD) U3.95(VDD33USB) U3.108(VDD) U3.121(VDD) U3.131(VDD) U3.144(VDD)
GND: C13.1 C14.1 C15.1 C16.1 C17.1 C18.1 C19.1 C20.1 C21.1 C22.1 C23.1 C24.1 C25.1 C27.1 C28.1 C29.1 C30.1 C31.1 C32.1 C33.1 C34.1 C35.1 C36.1 D4.2(A) D6.1 D7.1 J2.4 J2.P1 J2.P2 R8.2 R13.2 R18.1 SW2.2 SW2.3 U3.16(VSS) U3.31(VSSA) U3.38(VSS) U3.51(VSS) U3.61(VSS) U3.83(VSS) U3.94(VSS) U3.107(VSS) U3.120(VSS) U3.130(VSS) X1.2 X1.4
BOOT0: J2.7 R13.1 SW1.2 SW1.3 U3.138(BOOT0)
CAN_RX: U3.114(PD0)
CAN_TX: U3.115(PD1)
DOUT_N: U3.103(PA11)
DOUT_P: U3.104(PA12)
ESC_DISCONNECT: U3.69(PB10)
ESC_GPIO: R12.1 U3.78(PD9)
ESC_SEL: U3.70(PB11)
ETH_INTn: U3.56(PG0)
ETH_MISO: U3.20(PF8)
ETH_MOSI: U3.21(PF9)
ETH_RSTn: U3.57(PG1)
ETH_SCLK: U3.19(PF7)
ETH_SCSN: U3.18(PF6)
FMU_UART1_RX: U3.137(PB7)
FMU_UART1_TX: U3.136(PB6)
FRAM_CS: U3.3(PE4)
FRAM_MISO: U3.4(PE5)
FRAM_MOSI: R11.1
FRAM_SCK: R10.1
GPS_RX_SEL: U3.54(PF14)
GPS_TX_SEL: U3.55(PF15)
HITL2PDB_GPIO: U3.63(PE10)
HITL_DSHOT1: U3.60(PE9)
HITL_DSHOT2: U3.64(PE11)
HITL_DSHOT3: U3.66(PE13)
HITL_DSHOT4: U3.67(PE14)
HITL_GPS_RX: U3.97(PC7)
HITL_GPS_TX: U3.96(PC6)
HITL_MAG_SCL: U3.100(PA8)
HITL_MAG_SDA: U3.99(PC9)
HITL_PDB_UART_RX: U3.58(PE7)
HITL_PDB_UART_TX: U3.59(PE8)
HITL_RF_UART_RX: U3.141(PE0)
HITL_RF_UART_TX: U3.142(PE1)
I2C1_SCL: U3.139(PB8)
I2C1_SDA: U3.140(PB9)
I2C4_SCL: U3.81(PD12)
I2C4_SDA: U3.82(PD13)
LED: D8.2(POS) U3.26(PC0)
MAG_SCL_SEL: U3.49(PF11)
MAG_SDA_SEL: U3.50(PF12)
NRST: C35.2 D4.1(K) J2.6 SW2.1 SW2.4 U3.25(~{RST})
PB0: U3.46(PB0)
PB1: U3.47(PB1)
PB2: U3.48(PB2)
PC1: U3.27(PC1)
PC2_C: U3.28(PC2_C)
PC3_C: U3.29(PC3_C)
PC14_OSC32_IN: C32.2 U3.8(PC14/OSC32_IN) Y1.1
PC15_OSC32_OUT: C33.2 U3.9(PC15/OSC32_OUT) Y1.2
PDB_DISCONNECT: U3.65(PE12)
PDB_SEL: U3.68(PE15)
PF2: U3.12(PF2)
PF3: U3.13(PF3)
PF4: U3.14(PF4)
PF5: U3.15(PF5)
PF10: U3.22(PF10)
PF13: U3.53(PF13)
PG3: U3.88(PG3)
PG4: U3.89(PG4)
PG5: U3.90(PG5)
PG6: U3.91(PG6)
PH0_OSC_IN: C30.2 U3.23(PH0/OSC_IN) X1.1
PH1_OSC_OUT: C31.2 U3.24(PH1/OSC_OUT) X1.3
RF_RX_SEL: U3.44(PC4)
RF_TX_SEL: U3.45(PC5)
RGB_B: R14.2 U3.85(PD14)
RGB_G: R16.2 U3.86(PD15)
RGB_R: R17.2 U3.87(PG2)
SD_CLK: U3.74(PB13)
SD_CMD: U3.76(PB15)
SD_DATA0: U3.75(PB14)
SD_DATA3: U3.73(PB12)
SD_DET: U3.92(PG7)
SPI1_CS: U3.40(PA4)
SPI1_MISO: R15.1
SPI1_MOSI: U3.43(PA7)
SPI1_SCK: U3.41(PA5)
SPI3_CS: U3.110(PA15)
SPI3_MISO: U3.112(PC11)
SPI3_MOSI: U3.113(PC12)
SPI3_SCK: U3.111(PC10)
SPI6_CS: U3.126(PG11)
SPI6_MISO: U3.127(PG12)
SPI6_MOSI: U3.129(PG14)
SPI6_SCK: U3.128(PG13)
SWCLK: D7.2 J2.3 U3.109(PA14(JTCK/SWCLK))
SWDIO: D6.2 J2.2 U3.105(PA13(JTMS-SWDIO))
SWO: J2.8 U3.133(PB3(JTDO/TRACESWO))
TELEM: U3.79(PD10)
UART4_RX: U3.35(PA1)
UART4_TX: U3.34(PA0)
USART2_RX: U3.37(PA3)
USART2_TX: U3.36(PA2)
USB_VBUS_SNS: U3.101(PA9)
NetC29_2: C29.2 U3.106(VCAP)
NetC36_2: C36.2 U3.71(VCAP)
NetD5_B: D5.B R14.1
NetD5_G: D5.G R16.1
NetD5_R: D5.R R17.1
NetD8_1: D8.1(NEG) R18.2
NetR8_1: R8.1 R9.2 U3.143(PDR_ON)
NetR10_2: R10.2 U3.1(PE2)
NetR11_2: R11.2 U3.5(PE6)
NetR15_2: R15.2 U3.42(PA6)

Not connected (* = marked no-connect by the designer): J2 1*; U3 2(PE3)* 7(PC13) 10(PF0)* 11(PF1)* 77(PD8)* 80(PD11)* 93(PG8)* 98(PC8)* 102(PA10)* 116(PD2)* 117(PD3)* 118(PD4)* 119(PD5)* 122(PD6)* 123(PD7)* 124(PG9)* 125(PG10)* 132(PG15)* 134(PB4(~{JTRST}))* 135(PB5)*

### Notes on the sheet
- STM32H743ZIT6
- DECOUPLING STM32H7
- [PLACE NEAR VDD PINS & ]
- HSE
- LSE
- (near U3) UART8
- (near U3) I2C1
- (near U3) SPI6
- (near U3) FDCAN1
- (near U3) SPI3
- (near Y1) LSE
- (near U3) SPI4
- (near U3) USART1
- (near U3) I2C3
- (near U3) USART6
- (near U3) SPI5
- NRST & BOOT
- (near U3) USART3
- (near U3) I2C4
- (near U3) SPI2
- (near U3) USART2/UART4
- (near U3) SPI1
- (near U3) TIM3CH3
- (near U3) UART7
- (near U3) TIM1CH1-4
- (near U3) I2C2
- R12 CAN BE INSTALLED TO ENABLE 3 WAY COMMUNICATION ON 1 WIRE B/W FMU, ESC, AND HITL
- RGB LED
- PRGM CONN
- -
- 3
- 7

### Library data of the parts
C13-C25 C27-C36 = 0603_C
D4 = ESDALC6V1-1U2: - Clamp - Ipp Tvs Diode Surface Mount ST0201; MF: STMicroelectronics
D5 = MHS110FRGBCT: RAVE RAVE RAVE / COMMON ANODE
D6 D7 = LESD5D5.0CT1G: as D3 on sheet HITL (PWR) SH2
D8 = 0603_LED_BLU
J2 = SM08B-SRSS-TB: SH Series 8 Position 1 mm Pitch Surface Mount Side Entry Shrouded Header; MF: {'manufacturer': u'JST Sales America Inc.'}
R8-R18 = 0603_R
SW1 SW2 = KMR221GLFS: Switch Tactile N.O. SPST Button Gull Wing 0.05A 32VDC 1VA 200000Cycles 2N SMD Automotive T/R; MF: CK
U3 = STM32H743ZIT6: ARMÂ® CortexÂ®-M7 STM32H7 Microcontroller IC 32-Bit Single-Core 480MHz 2MB (2M x 8) FLASH 144-LQFP (20x20); MF: STMicroelectronics
X1 = CS11321-25M: Description; Manufacturer_Name: NDK
Y1 = NX3215SA-32.768KHZ-EXS00A-MU00525: 32.768 kHz - Crystal 6pF 50 kOhms 2-SMD, No Lead; MF: NDK America,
